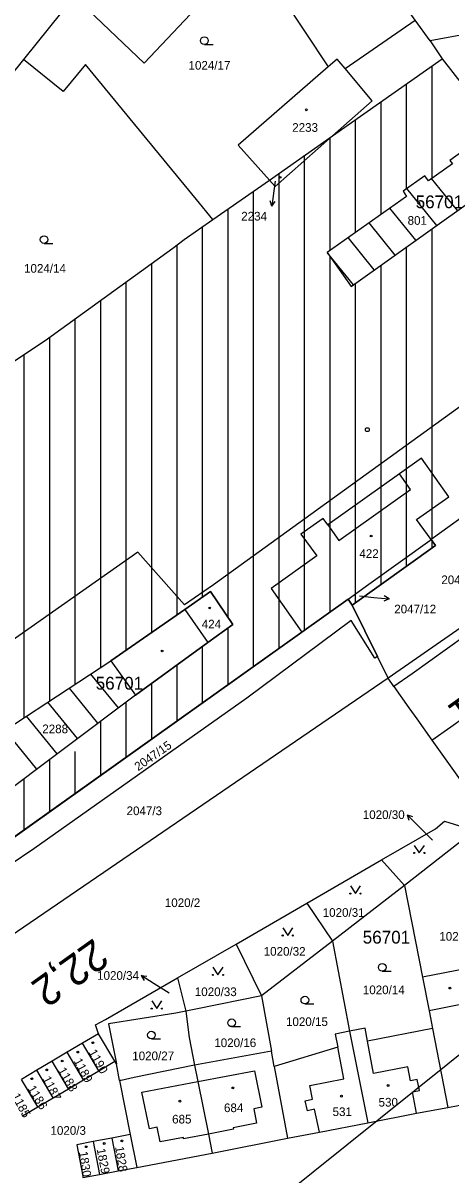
# Model space of a CAD drawing. Extents: x -794765 to -785424, y -1118958 to -1108731.
# Drawn here: x -792219.4 to -792135.5, y -1109922.9 to -1109697 of the extents above; entities that cross this region are included whole.
import ezdxf

# ---------------------------------------------------------------- set-up
doc = ezdxf.new("R2010")
doc.units = 0
for name, color, linetype in [('Level 66', 7, 'Continuous'), ('Level 71', 7, 'Continuous'), ('Level 73', 7, 'Continuous'), ('Level 75', 7, 'Continuous'), ('Level 76', 7, 'Continuous'), ('Level 77', 7, 'Continuous'), ('Level 78', 7, 'Continuous'), ('Level 79', 7, 'Continuous'), ('Level 80', 7, 'Continuous'), ('Level 81', 7, 'Continuous'), ('Vrstva 1', 7, 'Continuous'), ('Vrstva 53', 7, 'Continuous')]:
    doc.layers.add(name, color=color, linetype=linetype)

msp = doc.modelspace()

# ---------------------------------------------------------------- linework, layer by layer
at = {"layer": 'Level 66'}
for p, q in [((-792183.87, -1109701.22), (-792182.12, -1109701.22)), ((-792215.3, -1109740.23), (-792213.55, -1109740.23)), ((-792148.98, -1109882.92), (-792147.23, -1109882.92)), ((-792164.16, -1109889.35), (-792162.41, -1109889.35)), ((-792178.54, -1109893.8), (-792176.79, -1109893.8)), ((-792194.25, -1109896.2), (-792192.5, -1109896.2))]:
    msp.add_line(p, q, dxfattribs=at)
for points in [[(-792142.72, -1109858.25), (-792141.72, -1109859.75), (-792140.72, -1109858.25)], [(-792155.24, -1109866.21), (-792154.24, -1109867.71), (-792153.24, -1109866.21)], [(-792168.51, -1109874.43), (-792167.51, -1109875.93), (-792166.51, -1109874.43)], [(-792182.2, -1109882.15), (-792181.2, -1109883.65), (-792180.2, -1109882.15)], [(-792194.2, -1109888.75), (-792193.2, -1109890.25), (-792192.2, -1109888.75)]]:
    msp.add_lwpolyline(points, dxfattribs=at)
for centre, radius in [((-792183.87, -1109700.47), 0.75), ((-792215.3, -1109739.48), 0.75), ((-792142.72, -1109859.75), 0.1), ((-792140.72, -1109859.75), 0.1), ((-792155.24, -1109867.71), 0.1), ((-792153.24, -1109867.71), 0.1), ((-792168.51, -1109875.93), 0.1), ((-792166.51, -1109875.93), 0.1), ((-792148.98, -1109882.17), 0.75), ((-792182.2, -1109883.65), 0.1), ((-792180.2, -1109883.65), 0.1), ((-792164.16, -1109888.6), 0.75), ((-792194.2, -1109890.25), 0.1), ((-792192.2, -1109890.25), 0.1), ((-792178.54, -1109893.05), 0.75), ((-792194.25, -1109895.45), 0.75)]:
    msp.add_circle(centre, radius, dxfattribs=at)
at = {"layer": 'Level 71'}
msp.add_lwpolyline([(-791938.08, -1109742.36), (-792598.01, -1110271.46), (-792786.15, -1110036.8), (-792126.22, -1109507.7)], close=True, dxfattribs=at)
at = {"layer": 'Level 75'}
for p, q in [((-792180.81, -1109673.54), (-792159.56, -1109705.6)), ((-792139.61, -1109700.53), (-792137.25, -1109704.07)), ((-792219.35, -1109704.16), (-792293.96, -1109796.98)), ((-792158.73, -1109719.12), (-792137.25, -1109704.07)), ((-792137.25, -1109704.07), (-792130.48, -1109712.65)), ((-792171.12, -1109727.8), (-792158.73, -1109719.12)), ((-792182.21, -1109735.57), (-792171.12, -1109727.8)), ((-792164.73, -1109816.44), (-792155.68, -1109810)), ((-792155.68, -1109810), (-792154.86, -1109811.14)), ((-792154.86, -1109811.14), (-792149.91, -1109821.24)), ((-792246.55, -1109874.61), (-792164.73, -1109816.44)), ((-792147.85, -1109825.45), (-792149.91, -1109821.24)), ((-792202.2, -1109822.1), (-792197.4, -1109828.81)), ((-792147.85, -1109825.45), (-792244.24, -1109891.34)), ((-792146.7, -1109827.09), (-792147.85, -1109825.45)), ((-792130.85, -1109855.33), (-792144.6, -1109866.13)), ((-792163.8, -1109869.62), (-792149.1, -1109861.11)), ((-792149.1, -1109861.11), (-792144.6, -1109866.13)), ((-792144.6, -1109866.13), (-792158.71, -1109877.05)), ((-792144.6, -1109866.13), (-792141.07, -1109884.12)), ((-792177.65, -1109877.63), (-792163.8, -1109869.62)), ((-792163.8, -1109869.62), (-792158.71, -1109877.05)), ((-792189.12, -1109884.23), (-792177.65, -1109877.63)), ((-792177.65, -1109877.63), (-792172.69, -1109887.78)), ((-792158.71, -1109877.05), (-792172.69, -1109887.78)), ((-792158.71, -1109877.05), (-792155.38, -1109894.7)), ((-792189.12, -1109884.23), (-792187.51, -1109890.76)), ((-792172.69, -1109887.78), (-792170.71, -1109898.62)), ((-792204.62, -1109895.19), (-792207.76, -1109897.06)), ((-792201.42, -1109900.59), (-792204.62, -1109895.19)), ((-792139.11, -1109894.16), (-792136.09, -1109909.62)), ((-792207.76, -1109897.06), (-792210.75, -1109898.83)), ((-792204.56, -1109902.45), (-792207.76, -1109897.06)), ((-792213.74, -1109900.59), (-792216.72, -1109902.36)), ((-792210.75, -1109898.83), (-792213.74, -1109900.59)), ((-792210.54, -1109905.99), (-792213.74, -1109900.59)), ((-792207.56, -1109904.22), (-792210.75, -1109898.83)), ((-792204.56, -1109902.45), (-792201.42, -1109900.59)), ((-792201.11, -1109901.1), (-792201.42, -1109900.59)), ((-792170.71, -1109898.62), (-792185.77, -1109901.33)), ((-792170.17, -1109901.6), (-792170.71, -1109898.62)), ((-792216.72, -1109902.36), (-792219.71, -1109904.13)), ((-792213.53, -1109907.76), (-792216.72, -1109902.36)), ((-792207.56, -1109904.22), (-792204.56, -1109902.45)), ((-792200.48, -1109904.39), (-792201.11, -1109901.1)), ((-792170.17, -1109901.6), (-792167.58, -1109915.69)), ((-792216.52, -1109909.52), (-792219.71, -1109904.13)), ((-792210.54, -1109905.99), (-792207.56, -1109904.22)), ((-792200.48, -1109904.39), (-792198.4, -1109914.97)), ((-792213.53, -1109907.76), (-792210.54, -1109905.99)), ((-792219.5, -1109911.29), (-792216.52, -1109909.52)), ((-792216.52, -1109909.52), (-792213.53, -1109907.76)), ((-792202.02, -1109915.66), (-792205.67, -1109916.35)), ((-792205.67, -1109916.35), (-792204.45, -1109922.79)), ((-792198.4, -1109914.97), (-792202.02, -1109915.66)), ((-792202.02, -1109915.66), (-792200.79, -1109922.09)), ((-792198.4, -1109914.97), (-792197.14, -1109921.4)), ((-792182.33, -1109918.59), (-792167.58, -1109915.69)), ((-792197.14, -1109921.4), (-792182.33, -1109918.59)), ((-792204.45, -1109922.79), (-792200.79, -1109922.09)), ((-792200.79, -1109922.09), (-792197.14, -1109921.4))]:
    msp.add_line(p, q, dxfattribs=at)
for points in [[(-792187.37, -1109674.13), (-792176.46, -1109684.49), (-792195.66, -1109704.89), (-792206.56, -1109694.48)], [(-792139.61, -1109700.53), (-792142.53, -1109696.46), (-792154.82, -1109679.25)], [(-792206.56, -1109694.48), (-792209.4, -1109691.78), (-792219.35, -1109704.16)], [(-792126.16, -1109694.83), (-792131.81, -1109699.06), (-792139.61, -1109700.53)], [(-792182.21, -1109735.57), (-792185.42, -1109731.65), (-792207.17, -1109705.16), (-792211.55, -1109710.42), (-792219.35, -1109704.16)], [(-792158.73, -1109719.12), (-792150.95, -1109712.28), (-792156.26, -1109705.94), (-792157.82, -1109704.08), (-792159.56, -1109705.6)], [(-792159.56, -1109705.6), (-792177.21, -1109720.99), (-792171.12, -1109727.8)], [(-792171.12, -1109727.8), (-792170.01, -1109729.04), (-792158.73, -1109719.12)], [(-792139.92, -1109727.96), (-792140.61, -1109726.97), (-792144.91, -1109730.01), (-792144.21, -1109731), (-792159.76, -1109741.99), (-792155.1, -1109748.67), (-792131.63, -1109731.96), (-792131.14, -1109732.66), (-792127.76, -1109730.25), (-792128.26, -1109729.56), (-792122.8, -1109725.68), (-792127.44, -1109719.13), (-792132.86, -1109722.97), (-792133.35, -1109722.27), (-792135.73, -1109723.95), (-792135.23, -1109724.65), (-792139.92, -1109727.96)], [(-792226.53, -1109766.83), (-792215.1, -1109759.26), (-792190.07, -1109741.13), (-792187.8, -1109739.49), (-792182.21, -1109735.57)], [(-792088.89, -1109762.3), (-792112.22, -1109778.74), (-792129.24, -1109790.96), (-792130.77, -1109792.06), (-792139.4, -1109798.31)], [(-792139.4, -1109798.31), (-792142.25, -1109794.38), (-792135.9, -1109789.9), (-792141.29, -1109782.35), (-792145.59, -1109785.4), (-792159.68, -1109795.39), (-792160.54, -1109794.19), (-792164.93, -1109797.25), (-792161.84, -1109801.51), (-792170.75, -1109807.89), (-792164.73, -1109816.44)], [(-792155.68, -1109810), (-792151.63, -1109807.06), (-792139.68, -1109798.51), (-792139.4, -1109798.31)], [(-792154.86, -1109811.14), (-792138.54, -1109799.49), (-792139.4, -1109798.31)], [(-792119.78, -1109808.18), (-792120.9, -1109806.8), (-792147.85, -1109825.45)], [(-792197.4, -1109828.81), (-792183.19, -1109818.5), (-792178.27, -1109814.93), (-792182.67, -1109808.46), (-792187.68, -1109812.04), (-792202.2, -1109822.1)], [(-792121.37, -1109809.32), (-792125.81, -1109812.22), (-792143.12, -1109824.61), (-792146.7, -1109827.09)], [(-792149.91, -1109821.24), (-792150.43, -1109821.57), (-792155.08, -1109814.18), (-792175.53, -1109829.37), (-792217.28, -1109858.93), (-792231.29, -1109868.36), (-792246.55, -1109874.61)], [(-792197.4, -1109828.81), (-792224.99, -1109849.52), (-792231.36, -1109841.16), (-792202.2, -1109822.1)], [(-792146.7, -1109827.09), (-792143.74, -1109831.31), (-792142.22, -1109833.47), (-792139.27, -1109837.66), (-792132.41, -1109847.24), (-792127.98, -1109853)], [(-792149.1, -1109861.11), (-792138.53, -1109855), (-792136.75, -1109853.52), (-792131.07, -1109855.27), (-792130.85, -1109855.33)], [(-792125.37, -1109880.3), (-792130.03, -1109881.49), (-792129.95, -1109881.94), (-792141.07, -1109884.12)], [(-792204.62, -1109895.19), (-792205.19, -1109893.47), (-792203.27, -1109892.37), (-792189.12, -1109884.23)], [(-792141.07, -1109884.12), (-792139.79, -1109890.67), (-792139.11, -1109894.16)], [(-792172.69, -1109887.78), (-792185.54, -1109890.37), (-792187.51, -1109890.76)], [(-792187.51, -1109890.76), (-792189.46, -1109891.15), (-792202.65, -1109893.23), (-792201.11, -1109901.1)], [(-792187.51, -1109890.76), (-792186.82, -1109895.94), (-792185.77, -1109901.33)], [(-792155.38, -1109894.7), (-792158.21, -1109895.25), (-792157.72, -1109897.8), (-792170.17, -1109901.6)], [(-792139.11, -1109894.16), (-792151.86, -1109896.66), (-792152.34, -1109894.11), (-792155.38, -1109894.7)], [(-792155.38, -1109894.7), (-792154.89, -1109897.3), (-792151.83, -1109912.63)], [(-792185.77, -1109901.33), (-792197.65, -1109903.78), (-792200.21, -1109904.33), (-792200.48, -1109904.39)], [(-792185.77, -1109901.33), (-792185.12, -1109904.56), (-792183.07, -1109914.88), (-792182.33, -1109918.59)], [(-792136.09, -1109909.62), (-792130.02, -1109908.46), (-792120.5, -1109906.64)], [(-792151.83, -1109912.63), (-792142.25, -1109910.79), (-792136.09, -1109909.62)], [(-792167.58, -1109915.69), (-792161.31, -1109914.51), (-792151.83, -1109912.63)], [(-792205.67, -1109916.35), (-792208.89, -1109916.96), (-792207.73, -1109923.09)], [(-792207.73, -1109923.09), (-792207.67, -1109923.4), (-792204.45, -1109922.79)]]:
    msp.add_lwpolyline(points, dxfattribs=at)
at = {"layer": 'Level 77'}
for p, q in [((-792156.26, -1109705.94), (-792142.53, -1109696.46)), ((-792143.42, -1109788.47), (-792145.59, -1109785.4)), ((-792157.49, -1109798.49), (-792143.42, -1109788.47)), ((-792159.68, -1109795.39), (-792157.49, -1109798.49)), ((-792187.68, -1109812.04), (-792183.19, -1109818.5)), ((-792135.56, -1109835), (-792130.12, -1109831.1)), ((-792139.27, -1109837.66), (-792135.56, -1109835)), ((-792132.94, -1109889.33), (-792139.79, -1109890.67)), ((-792156.52, -1109904.06), (-792157.72, -1109897.8)), ((-792150.67, -1109902.98), (-792151.86, -1109896.66)), ((-792185.12, -1109904.56), (-792174.06, -1109902.44)), ((-792174.06, -1109902.44), (-792172.6, -1109909.57)), ((-792143.96, -1109901.68), (-792150.67, -1109902.98)), ((-792143.45, -1109904.41), (-792143.96, -1109901.68)), ((-792196.12, -1109906.67), (-792185.12, -1109904.56)), ((-792163.2, -1109905.35), (-792156.52, -1109904.06)), ((-792142.11, -1109904.16), (-792143.45, -1109904.41)), ((-792141.71, -1109906.3), (-792142.11, -1109904.16)), ((-792194.65, -1109913.84), (-792196.12, -1109906.67)), ((-792162.64, -1109908.05), (-792163.2, -1109905.35)), ((-792143.05, -1109906.55), (-792141.71, -1109906.3)), ((-792142.25, -1109910.79), (-792143.05, -1109906.55)), ((-792172.6, -1109909.57), (-792174.15, -1109909.89)), ((-792164.07, -1109908.34), (-792162.64, -1109908.05)), ((-792163.67, -1109910.29), (-792164.07, -1109908.34)), ((-792174.15, -1109909.89), (-792173.64, -1109912.74)), ((-792162.24, -1109910), (-792163.67, -1109910.29)), ((-792161.31, -1109914.51), (-792162.24, -1109910)), ((-792193.15, -1109913.53), (-792194.65, -1109913.84)), ((-792192.52, -1109916.41), (-792193.15, -1109913.53)), ((-792178.17, -1109913.93), (-792183.07, -1109914.88)), ((-792173.64, -1109912.74), (-792178.22, -1109913.63)), ((-792178.22, -1109913.63), (-792178.17, -1109913.93)), ((-792187.99, -1109915.53), (-792192.52, -1109916.41)), ((-792187.94, -1109915.82), (-792187.99, -1109915.53)), ((-792183.07, -1109914.88), (-792187.94, -1109915.82))]:
    msp.add_line(p, q, dxfattribs=at)
at = {"layer": 'Level 78'}
for p, q in [((-792139.2, -1109727.45), (-792139.2, -1109705.44)), ((-792144.2, -1109729.51), (-792144.2, -1109708.94)), ((-792149.2, -1109734.53), (-792149.2, -1109712.44)), ((-792154.2, -1109738.06), (-792154.2, -1109715.95)), ((-792159.2, -1109741.59), (-792159.2, -1109719.45)), ((-792164.2, -1109816.06), (-792164.2, -1109722.95)), ((-792169.2, -1109819.62), (-792169.2, -1109726.45)), ((-792134.22, -1109733.8), (-792139.3, -1109727.53)), ((-792174.2, -1109823.17), (-792174.2, -1109729.97)), ((-792138.3, -1109736.71), (-792144.16, -1109729.48)), ((-792179.2, -1109813.56), (-792179.2, -1109733.48)), ((-792142.38, -1109739.62), (-792147.48, -1109733.31)), ((-792184.2, -1109809.55), (-792184.2, -1109737)), ((-792146.46, -1109742.52), (-792151.58, -1109736.21)), ((-792139.2, -1109798.17), (-792139.2, -1109737.35)), ((-792150.54, -1109745.43), (-792155.67, -1109739.1)), ((-792189.2, -1109813.09), (-792189.2, -1109740.52)), ((-792154.62, -1109748.33), (-792159.76, -1109741.99)), ((-792144.2, -1109803.53), (-792144.2, -1109740.91)), ((-792194.2, -1109816.56), (-792194.2, -1109744.12)), ((-792159.2, -1109812.5), (-792159.2, -1109742.79)), ((-792149.2, -1109807.1), (-792149.2, -1109744.47)), ((-792199.2, -1109820.02), (-792199.2, -1109747.74)), ((-792154.2, -1109810.67), (-792154.2, -1109748.03)), ((-792204.2, -1109823.41), (-792204.2, -1109751.36)), ((-792209.2, -1109826.68), (-792209.2, -1109754.99)), ((-792214.2, -1109829.94), (-792214.2, -1109758.61)), ((-792219.2, -1109833.21), (-792219.2, -1109761.98)), ((-792139.2, -1109799.96), (-792139.2, -1109798.58)), ((-792179.2, -1109826.73), (-792179.2, -1109815.6)), ((-792184.2, -1109830.28), (-792184.2, -1109819.23)), ((-792189.2, -1109833.84), (-792189.2, -1109822.86)), ((-792200.73, -1109831.31), (-792206.12, -1109824.66)), ((-792204.73, -1109834.32), (-792210.32, -1109827.41)), ((-792194.2, -1109837.39), (-792194.2, -1109826.49)), ((-792208.74, -1109837.32), (-792214.53, -1109830.16)), ((-792199.2, -1109840.95), (-792199.2, -1109830.16)), ((-792212.74, -1109840.32), (-792218.74, -1109832.91)), ((-792204.2, -1109844.5), (-792204.2, -1109833.91)), ((-792216.74, -1109843.33), (-792222.95, -1109835.66)), ((-792214.2, -1109851.61), (-792214.2, -1109841.42)), ((-792209.2, -1109848.06), (-792209.2, -1109839.88)), ((-792219.2, -1109855.17), (-792219.2, -1109845.17))]:
    msp.add_line(p, q, dxfattribs=at)
at = {"layer": 'Level 79'}
for centre in [(-792163.87, -1109714.03), (-792169.02, -1109727.27), (-792141.82, -1109732.33), (-792151.16, -1109797.6), (-792182.82, -1109811.71), (-792192.16, -1109820.14), (-792135.73, -1109886.24), (-792205.73, -1109896.96), (-792211.73, -1109900.54), (-792208.7, -1109898.79), (-792214.78, -1109902.28), (-792217.71, -1109904.02), (-792147.84, -1109905.33), (-792178.29, -1109905.81), (-792156.99, -1109907.42), (-792188.66, -1109908.42), (-792203.5, -1109916.71), (-792200.03, -1109916.21), (-792207.03, -1109917.35)]:
    msp.add_circle(centre, 0.175, dxfattribs=at)
at = {"layer": 'Level 80'}
for p, q in [((-792169.95, -1109728.01), (-792170.22, -1109729.94)), ((-792170.22, -1109729.94), (-792170.64, -1109732.91)), ((-792170.64, -1109732.91), (-792170.99, -1109731.85)), ((-792170.64, -1109732.91), (-792170, -1109731.99)), ((-792153.46, -1109809.36), (-792150.62, -1109809.64)), ((-792150.62, -1109809.64), (-792147.64, -1109809.95)), ((-792147.64, -1109809.95), (-792148.68, -1109810.35)), ((-792147.64, -1109809.95), (-792148.58, -1109809.35)), ((-792142, -1109854.36), (-792144.12, -1109852.24)), ((-792144.12, -1109852.24), (-792143.06, -1109852.59)), ((-792144.12, -1109852.24), (-792143.77, -1109853.3)), ((-792139.15, -1109857.21), (-792142, -1109854.36)), ((-792193.69, -1109885.38), (-792196.23, -1109883.79)), ((-792196.23, -1109883.79), (-792195.12, -1109883.9)), ((-792196.23, -1109883.79), (-792195.65, -1109884.75)), ((-792190.75, -1109887.24), (-792193.69, -1109885.38))]:
    msp.add_line(p, q, dxfattribs=at)
at = {"layer": 'Level 81'}
for points in [[(-792227.74, -1109767.63), (-792215.1, -1109759.26), (-792190.07, -1109741.13), (-792187.8, -1109739.49), (-792182.21, -1109735.57), (-792171.12, -1109727.8), (-792170.01, -1109729.04), (-792158.73, -1109719.12), (-792137.25, -1109704.07), (-792130.48, -1109712.65), (-792120.92, -1109725.39), (-792116.05, -1109731.95), (-792110.51, -1109729.29), (-792110.1, -1109729.86), (-792106.76, -1109727.49), (-792082.74, -1109715.97), (-792092.71, -1109704.13), (-792077.28, -1109690.45)], [(-792120.9, -1109806.8), (-792147.85, -1109825.45), (-792149.91, -1109821.24), (-792154.86, -1109811.14), (-792138.54, -1109799.49), (-792139.4, -1109798.31), (-792142.25, -1109794.38), (-792135.9, -1109789.9), (-792141.29, -1109782.35), (-792145.59, -1109785.4), (-792159.68, -1109795.39), (-792160.54, -1109794.19), (-792164.93, -1109797.25), (-792161.84, -1109801.51), (-792170.75, -1109807.89), (-792164.73, -1109816.44), (-792246.55, -1109874.61)]]:
    msp.add_lwpolyline(points, dxfattribs=at)
for points in [[(-792144.91, -1109730.01), (-792144.21, -1109731), (-792159.76, -1109741.99), (-792155.1, -1109748.67), (-792131.63, -1109731.96), (-792131.14, -1109732.66), (-792127.76, -1109730.25), (-792128.26, -1109729.56), (-792122.8, -1109725.68), (-792127.44, -1109719.13), (-792132.86, -1109722.97), (-792133.35, -1109722.27), (-792135.73, -1109723.95), (-792135.23, -1109724.65), (-792139.92, -1109727.96), (-792140.61, -1109726.97)], [(-792202.2, -1109822.1), (-792187.68, -1109812.04), (-792182.67, -1109808.46), (-792178.27, -1109814.93), (-792183.19, -1109818.5), (-792197.4, -1109828.81), (-792224.99, -1109849.52), (-792231.36, -1109841.16)]]:
    msp.add_lwpolyline(points, close=True, dxfattribs=at)
at = {"layer": 'Vrstva 1'}
for q in [(-792262.89, -1109847.12), (-792187.76, -1109811.11)]:
    msp.add_line((-792196.9, -1109800.79), q, dxfattribs=at)
for points in [[(-792036.03, -1109711.9), (-792041.12, -1109704.75), (-792068.33, -1109725.02), (-792101.91, -1109749.26), (-792182.09, -1109807.15)], [(-792182.09, -1109807.15), (-792187.76, -1109811.11)]]:
    msp.add_lwpolyline(points, dxfattribs=at)
msp.add_circle((-792151.91, -1109776.75), 0.375, dxfattribs=at)
at = {"layer": 'Vrstva 53'}
for points in [[(-792226.53, -1109766.83), (-792215.1, -1109759.26), (-792190.07, -1109741.13), (-792187.8, -1109739.49), (-792182.21, -1109735.57), (-792171.12, -1109727.8), (-792158.73, -1109719.12), (-792137.25, -1109704.07), (-792130.48, -1109712.65), (-792129.14, -1109711.27), (-792119.15, -1109724.06), (-792100.25, -1109709.81), (-792096.91, -1109714.15), (-792092.06, -1109710.49), (-792095.42, -1109706.17), (-792092.71, -1109704.13), (-792082.74, -1109715.97), (-792057.33, -1109700.37), (-792051.73, -1109696.36), (-792038.26, -1109686.52)], [(-792130.77, -1109792.06), (-792139.4, -1109798.31), (-792138.54, -1109799.49), (-792154.86, -1109811.14), (-792155.68, -1109810), (-792164.73, -1109816.44), (-792246.55, -1109874.61)]]:
    msp.add_lwpolyline(points, dxfattribs=at)
msp.add_lwpolyline([(-792182.67, -1109808.46), (-792187.68, -1109812.04), (-792202.2, -1109822.1), (-792197.4, -1109828.81), (-792183.19, -1109818.5), (-792178.27, -1109814.93)], close=True, dxfattribs=at)

# ---------------------------------------------------------------- texts
at = {"layer": 'Level 73'}
for s, rotation, p in [('22,1', 215.3979, (-792123.75, -1109822.08)), ('22,2', 215.4652, (-792205.52, -1109876.32))]:
    msp.add_text(s, height=6, rotation=rotation, dxfattribs=at).set_placement(p)
at = {"layer": 'Level 76'}
for s, p in [('1024/17', (-792186.97, -1109706.16)), ('2233', (-792166.64, -1109718.35)), ('2234', (-792176.64, -1109735.74)), ('801', (-792144.01, -1109736.58)), ('1024/14', (-792219.23, -1109745.98)), ('422', (-792153.47, -1109801.9)), ('2047/13', (-792137.4, -1109807.04)), ('2047/12', (-792146.63, -1109812.77)), ('424', (-792184.38, -1109815.72)), ('2288', (-792215.65, -1109836.27)), ('2047/3', (-792199.12, -1109852.33)), ('1020/30', (-792152.8, -1109853.09)), ('1020/2', (-792191.62, -1109870.35)), ('1020/31', (-792160.66, -1109872.27)), ('1020/13', (-792137.79, -1109876.95)), ('1020/32', (-792172.23, -1109879.89)), ('1020/34', (-792204.9, -1109884.62)), ('1020/33', (-792185.74, -1109887.81)), ('1020/14', (-792152.79, -1109887.44)), ('1020/15', (-792167.86, -1109893.68)), ('1020/16', (-792181.92, -1109897.81)), ('1020/27', (-792198.01, -1109900.38)), ('684', (-792180.02, -1109910.56)), ('531', (-792158.72, -1109911.33)), ('530', (-792149.7, -1109909.47)), ('685', (-792190.19, -1109912.79)), ('1020/3', (-792214.04, -1109915.01))]:
    msp.add_text(s, height=1.7, dxfattribs=at).set_placement(p)
for s, rotation, p in [('2047/15', 35, (-792196.83, -1109843.73)), ('1190', 299, (-792206.63, -1109898.81)), ('1189', 298, (-792209.54, -1109900.52)), ('1188', 300, (-792212.64, -1109902.36)), ('1187', 297, (-792215.66, -1109904.01)), ('1185', 298, (-792221.71, -1109907.37)), ('1186', 301, (-792218.59, -1109905.93)), ('1830', 279, (-792208.47, -1109918.36)), ('1829', 281, (-792205, -1109917.82)), ('1828', 279, (-792201.38, -1109917.38))]:
    msp.add_text(s, height=1.7, rotation=rotation, dxfattribs=at).set_placement(p)
at = {"layer": 'Level 81'}
for p in [(-792142.43, -1109733.33), (-792205.18, -1109827.71), (-792152.81, -1109877.51)]:
    msp.add_text('56701', height=2.5, dxfattribs=at).set_placement(p)

doc.saveas('drawing.dxf')
